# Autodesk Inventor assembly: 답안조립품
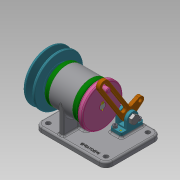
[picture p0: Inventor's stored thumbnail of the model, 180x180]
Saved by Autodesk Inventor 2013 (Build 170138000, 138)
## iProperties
Created: 2019-09
Part Number: 답안조립품
Document SubType Name: Assembly
Designer: Administrator
Mass: 1417.86 g
Surface Area: 1426.65 cm^2
Volume: 427.118 cm^3
Density: 3.31959 g/cm^3
Author: Administrator
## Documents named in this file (19)
- C:\Users\Administrator\Downloads\390904V1011\답안조립품.iam
- C:\Users\Administrator\Downloads\390904V1011\본체.ipt
- C:\Users\Administrator\Downloads\390904V1011\V-벨트풀리.ipt
- C:\Users\Administrator\Downloads\390904V1011\너트 M8.ipt
- C:\Users\Administrator\Downloads\390904V1011\너트 M10x1.ipt
- C:\Users\Administrator\Downloads\390904V1011\돌림판.ipt
- C:\Users\Administrator\Downloads\390904V1011\멈춤나사 M3x5.ipt
- C:\Users\Administrator\Downloads\390904V1011\베어링 6004.ipt
- C:\Users\Administrator\Downloads\390904V1011\볼트 M4.ipt
- C:\Users\Administrator\Downloads\390904V1011\오일 실 17 30 5.ipt
- C:\Users\Administrator\Downloads\390904V1011\와셔 8x15.5.ipt
- C:\Users\Administrator\Downloads\390904V1011\축.ipt
- C:\Users\Administrator\Downloads\390904V1011\커버.ipt
- C:\Users\Administrator\Downloads\390904V1011\크랭크.ipt
- C:\Users\Administrator\Downloads\390904V1011\키 4 x 4 x 8.ipt
- C:\Users\Administrator\Downloads\390904V1011\키 5 x 5 x 12.ipt
- C:\Users\Administrator\Downloads\390904V1011\핀 3 x 8.ipt
- C:\Users\Administrator\Downloads\390904V1011\힌지 축.ipt
- C:\Users\Administrator\Downloads\390904V1011\힌지.ipt
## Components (3 placed, 2 different names)
1. V-벨트풀리:1
2. 핀 3 x 8:1 — 플러쉬:2
3. 핀 3 x 8:2 — 플러쉬:3
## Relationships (2: Flush 2)
- 플러쉬:2 [Flush]: 핀 3 x 8:1
- 플러쉬:3 [Flush]: 핀 3 x 8:2
